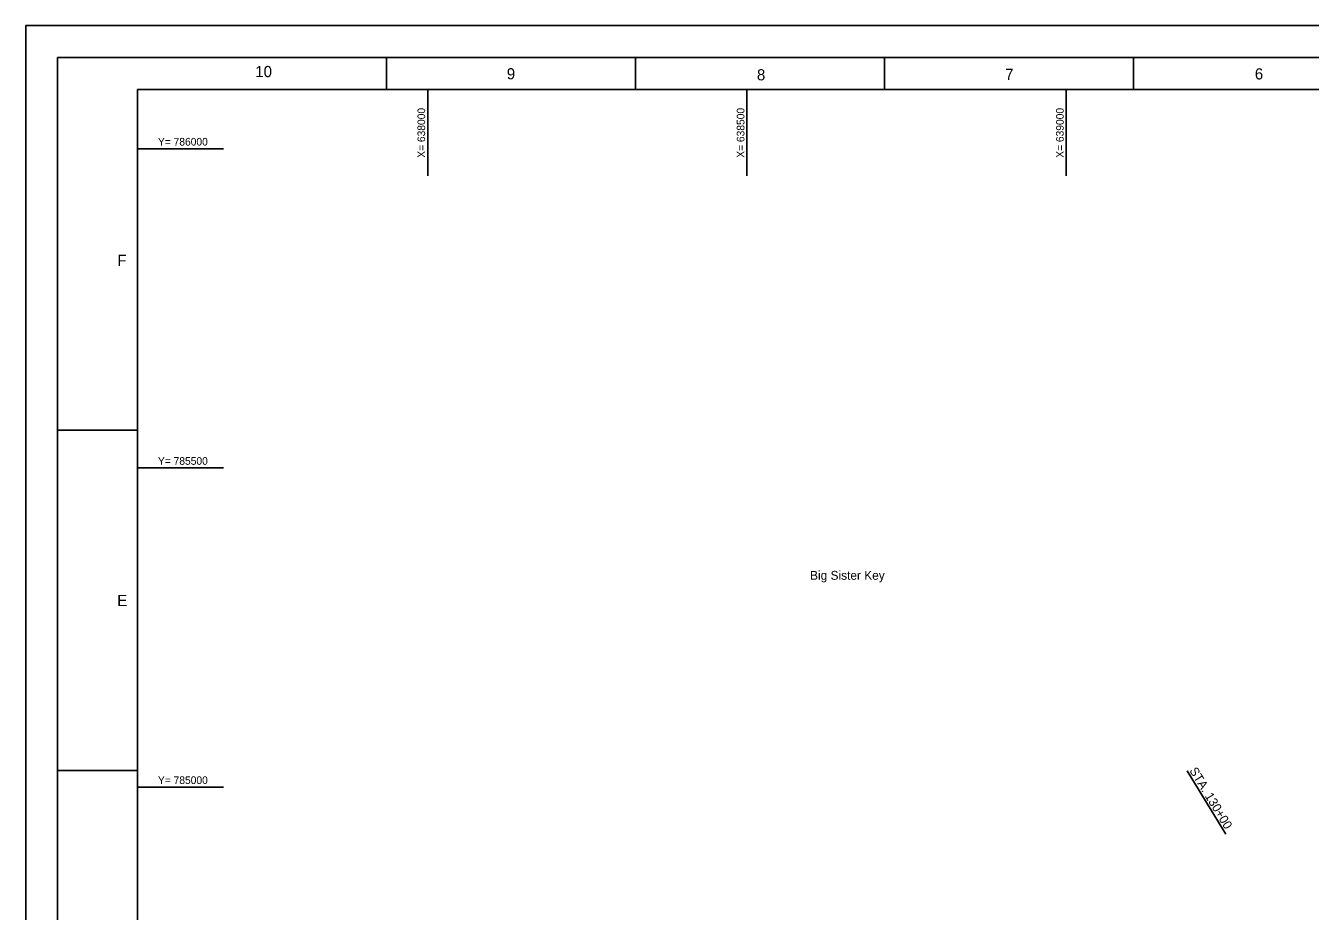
# Model space of a CAD drawing. Extents: x 637370 to 641771, y 782793 to 786193.
# Drawn here: x 637370 to 639382, y 784806 to 786193 of the extents above; entities that cross this region are included whole.
import ezdxf

# ---------------------------------------------------------------- set-up
doc = ezdxf.new("R2010")
doc.units = 0
for name, color, linetype in [('G-ANNO-NPLT', 7, 'Continuous'), ('G-ANNO-TTLB', 7, 'Continuous'), ('V-ALGN-TEXT', 7, 'Continuous'), ('V-SITE-IDEN', 7, 'Continuous'), ('V-TOPO-COOR-STAT', 7, 'Continuous')]:
    doc.layers.add(name, color=color, linetype=linetype)

msp = doc.modelspace()

# ---------------------------------------------------------------- linework, layer by layer
at = {"layer": 'G-ANNO-NPLT'}
msp.add_lwpolyline([(637370.5, 786192.8), (641770.5, 786192.8), (641770.5, 782792.8), (637370.5, 782792.8)], close=True, dxfattribs=at)
msp.add_lwpolyline([(637370.5, 786142.8), (637370.5, 786192.8), (637420.5, 786192.8)], dxfattribs=at)
at = {"layer": 'G-ANNO-TTLB'}
for p, q in [((637935.5, 786142.8), (637935.5, 786092.8)), ((638325.5, 786142.8), (638325.5, 786092.8)), ((638325.5, 786142.8), (638325.5, 786092.8)), ((638715.5, 786142.8), (638715.5, 786092.8)), ((639105.5, 786142.8), (639105.5, 786092.8)), ((637420.5, 785559.3), (637545.5, 785559.3)), ((637420.5, 785026), (637545.5, 785026))]:
    msp.add_line(p, q, dxfattribs=at)
for points in [[(637420.5, 782842.8), (641720.5, 782842.8), (641720.5, 786142.8), (637420.5, 786142.8)], [(641670.5, 786092.8), (637545.5, 786092.8), (637545.5, 782892.8), (641670.5, 782892.8)]]:
    msp.add_lwpolyline(points, close=True, dxfattribs=at)
at = {"layer": 'V-ALGN-TEXT'}
msp.add_line((639189.4, 785025.5), (639249.7, 784926.2), dxfattribs=at)
at = {"layer": 'V-TOPO-COOR-STAT'}
for p, q in [((638000, 785957.8), (638000, 786092.8)), ((638500, 785957.8), (638500, 786092.8)), ((639000, 785957.8), (639000, 786092.8)), ((637545.5, 786000), (637680.5, 786000)), ((637545.5, 785500), (637680.5, 785500)), ((637545.5, 785000), (637680.5, 785000))]:
    msp.add_line(p, q, dxfattribs=at)

# ---------------------------------------------------------------- texts
at = {"layer": 'G-ANNO-TTLB'}
for s, p in [('10', (637730.1, 786112.2)), ('9', (638123.9, 786108.7)), ('6', (639295.3, 786108.5)), ('8', (638515.6, 786107.1)), ('7', (638904.3, 786107.8)), ('F', (637514, 785816.4)), ('E', (637513.9, 785283.7))]:
    msp.add_text(s, height=17.5, dxfattribs=at).set_placement(p)
at = {"layer": 'V-ALGN-TEXT'}
msp.add_text('STA. 130+00', height=13.92, rotation=301.2715, dxfattribs=at).set_placement((639192.3, 785026.1))
at = {"layer": 'V-SITE-IDEN'}
msp.add_text('Big Sister Key', height=13.92, dxfattribs=at).set_placement((638598.8, 785324.9))
at = {"layer": 'V-TOPO-COOR-STAT'}
for s, p in [('X= 638000', (637996, 785985.9)), ('X= 638500', (638496, 785985.9)), ('X= 639000', (638996, 785985.9))]:
    msp.add_text(s, height=12, rotation=90, dxfattribs=at).set_placement(p)
for s, p in [('Y= 786000', (637577.6, 786005)), ('Y= 785500', (637577.6, 785505)), ('Y= 785000', (637577.6, 785005))]:
    msp.add_text(s, height=12, dxfattribs=at).set_placement(p)

doc.saveas('drawing.dxf')
